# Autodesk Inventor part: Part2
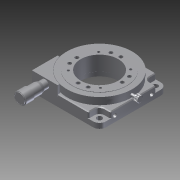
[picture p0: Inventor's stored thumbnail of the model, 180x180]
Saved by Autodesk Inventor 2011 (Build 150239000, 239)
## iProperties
Created: 2012-07
Part Number: Part2
Document SubType Name: Modeling
Designer: vadybininkas6
Density: 1 g/cm^3
Author: vadybininkas6
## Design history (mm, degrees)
feature "Base1"
body "Solid1"
